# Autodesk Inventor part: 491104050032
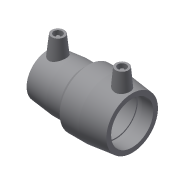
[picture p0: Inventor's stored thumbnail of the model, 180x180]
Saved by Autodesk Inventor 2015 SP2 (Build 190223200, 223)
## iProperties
Created: 2017-06
Part Number: 491104050032
Material: Generic
Description: PLASSON REDUCING COUPLER 50-32
Document SubType Name: Modeling
Designer: KIM
Mass: 54.8237 g
Surface Area: 155.252 cm^2
Volume: 54.8237 cm^3
Density: 1 g/cm^3
Appearance: Default
Author: KIM
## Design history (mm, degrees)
derived "491104.ipt"
feature "Solid1::491104.ipt"
tag "TaggingFeature1"
body "Solid1"
other parameters: "d_1" = 32, "D_1" = 45, "A_1" = 45, "d_2" = 12, "L_1" = 49, "A_" = 52, "D_" = 68, "d2" = 45, "d4" = 24, "d5" = 40.5, "d7" = 32, "d8" = 168 deg, "d10" = 16, "d11" = 5.33333, "d14" = 17.6296, "d18" = 32, "d19" = 2, "d20" = 168 deg, "d22" = 108.92847, "d25" = 135 deg, "d29" = 45, "d30" = 15, "d31" = 38, "d34" = 6 deg, "d35" = 15, "d38" = 27.4, "d39" = 5 deg, "d41" = 4, "d42" = 14, "d43" = 0, "d45" = 4, "d46" = 14, "d47" = 0, "d48" = 45, "d50" = 68, "d52" = 28.8, "d53" = 19.6, "d54" = 6.53333, "d55" = 168 deg, "d56" = 29.4, "d57" = 49, "d58" = 61.2, "d59" = 2, "d60" = 135 deg, "d61" = 52, "d62" = 15, "d64" = 4, "d66" = 5 deg, "d67" = 14, "d68" = 0, "d69" = 38, "d70" = 45, "d71" = 68, "d73" = 63.92, "d76" = 2, "d77" = 168 deg, "d79" = 2, "d80" = 49, "d81" = 28.8, "d82" = 42.3, "d83" = 120 deg, "d88" = 15, "d89" = 24.5, "d90" = 5 deg, "d92" = 4, "d93" = 14, "d94" = 0, "d95" = 3, "d96" = 0, "d97" = 3, "d98" = 0, "d99" = 11.6, "d100" = 2.9, "d101" = 41.031, "d102" = 20 deg, "d103" = 14.21, "d104" = 3.5525, "d105" = 62.0024, "d106" = 3.60705, "d107" = 3, "d108" = 0, "d109" = 3, "d110" = 0
